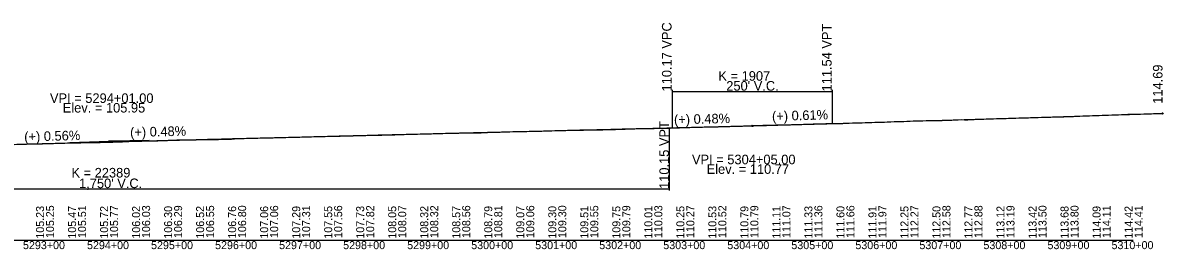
# Model space of a CAD drawing. Extents: x 2121671 to 2169879, y 557274 to 599957.
# Drawn here: x 2158834 to 2160615, y 592693 to 593048 of the extents above; entities that cross this region are included whole.
import ezdxf

# ---------------------------------------------------------------- set-up
doc = ezdxf.new("R2010")
doc.units = 0
for name, color, linetype in [('RD_DDB_GradeTX', 7, 'Continuous'), ('RD_DDB_Profile_EX', 7, 'Continuous'), ('RD_DDB_Profile_Lbl', 7, 'Continuous'), ('RD_DDB_Profile_PR', 7, 'Continuous'), ('RD_DDB_StaTX', 7, 'Continuous'), ('RD_DDB_StripGrade', 7, 'Continuous'), ('RD_DDB_VCLbl', 7, 'Continuous'), ('RD_GPK_Profile_Cell', 7, 'Continuous')]:
    doc.layers.add(name, color=color, linetype=linetype)

msp = doc.modelspace()

# ---------------------------------------------------------------- linework, layer by layer
at = {"layer": 'RD_DDB_GradeTX'}
for p, q in [((2159911.3, 592884.9), (2159972.2, 592886.3)), ((2160035.2, 592888.2), (2159974.2, 592886.4)), ((2158907.3, 592860.5), (2158968.2, 592862.2)), ((2159031.2, 592863.7), (2158970.2, 592862.2))]:
    msp.add_line(p, q, dxfattribs=at)
for centre in [(2160614, 592905.9), (2159973.2, 592886.3), (2158969.2, 592862.2)]:
    msp.add_circle(centre, 1, dxfattribs=at)
at = {"layer": 'RD_DDB_Profile_EX'}
for points in [[(2160004.8, 592887.7), (2160009.8, 592887.8), (2160014.8, 592887.9), (2160019.8, 592888), (2160024.8, 592888.1), (2160029.8, 592888.2), (2160034.8, 592888.3), (2160039.8, 592888.4), (2160044.8, 592888.5), (2160049.8, 592888.7), (2160054.8, 592888.8), (2160059.8, 592888.9), (2160064.8, 592889), (2160069.8, 592889.2), (2160074.8, 592889.3), (2160079.8, 592889.4), (2160084.8, 592889.5), (2160089.8, 592889.8), (2160094.8, 592889.9), (2160099.8, 592889.9), (2160104.8, 592890), (2160109.8, 592890.1), (2160114.8, 592890.3), (2160119.8, 592890.5), (2160124.8, 592890.7), (2160129.8, 592890.9), (2160134.8, 592891), (2160139.8, 592891.2), (2160144.8, 592891.3), (2160149.8, 592891.5), (2160154.8, 592891.6), (2160159.8, 592891.7), (2160164.8, 592891.9), (2160169.8, 592892.1), (2160174.8, 592892.3), (2160179.8, 592892.4), (2160184.8, 592892.6), (2160189.8, 592892.8), (2160194.8, 592893), (2160199.8, 592893.1), (2160204.8, 592893.3), (2160209.8, 592893.4), (2160214.8, 592893.6), (2160219.8, 592893.8), (2160224.8, 592894.1), (2160229.8, 592894.2), (2160234.8, 592894.3), (2160239.8, 592894.4), (2160244.8, 592894.5), (2160249.8, 592894.5), (2160254.8, 592894.6), (2160259.8, 592894.9), (2160264.8, 592895), (2160269.8, 592895), (2160274.8, 592895.1), (2160279.8, 592895.1), (2160284.8, 592895.4), (2160289.8, 592895.6), (2160294.8, 592895.8), (2160299.8, 592896.1), (2160304.8, 592895.9), (2160309.8, 592895.8), (2160314.8, 592896.1), (2160319.8, 592896.4), (2160324.8, 592896.8), (2160329.8, 592896.9), (2160334.8, 592897.1), (2160339.8, 592897.2), (2160344.8, 592897.4), (2160349.8, 592897.6), (2160354.8, 592897.7), (2160359.8, 592897.9), (2160364.8, 592898), (2160369.8, 592898.1), (2160374.8, 592898.3), (2160379.8, 592898.5), (2160384.8, 592898.6), (2160389.8, 592898.8), (2160394.8, 592898.9), (2160399.8, 592899.1), (2160404.8, 592899.1), (2160409.8, 592899.2), (2160414.8, 592899.4), (2160419.8, 592899.7), (2160424.8, 592899.8), (2160429.8, 592899.9), (2160434.8, 592900), (2160439.8, 592900.1), (2160444.8, 592900.3), (2160449.8, 592900.3), (2160454.8, 592900.6), (2160459.8, 592900.7), (2160464.8, 592900.8), (2160469.8, 592900.9), (2160474.8, 592901.1), (2160479.8, 592901.3), (2160484.8, 592901.6), (2160489.8, 592901.8), (2160494.8, 592902), (2160499.8, 592902.2), (2160504.8, 592902.4)], [(2160504.8, 592902.4), (2160509.8, 592902.6), (2160514.8, 592902.8), (2160519.8, 592903), (2160524.8, 592903.1), (2160529.8, 592903.3), (2160534.8, 592903.5), (2160539.8, 592903.7), (2160544.8, 592903.8), (2160549.8, 592904), (2160554.8, 592904.2), (2160559.8, 592904.4), (2160564.8, 592904.5), (2160569.8, 592904.6), (2160574.8, 592904.7), (2160579.8, 592904.9), (2160584.8, 592905), (2160589.8, 592905.1), (2160594.8, 592905.2), (2160599.8, 592905.5), (2160604.8, 592905.6), (2160609.8, 592905.8), (2160614, 592905.9)], [(2159004.8, 592862.3), (2159009.8, 592862.4), (2159014.8, 592862.5), (2159019.8, 592862.6), (2159024.8, 592862.7), (2159029.8, 592862.8), (2159034.8, 592862.9), (2159039.8, 592863), (2159044.8, 592863.2), (2159049.8, 592863.3), (2159054.8, 592863.4), (2159059.8, 592863.6), (2159064.8, 592863.8), (2159069.8, 592864), (2159074.8, 592864.3), (2159079.8, 592864.4), (2159084.8, 592864.4), (2159089.8, 592864.4), (2159094.8, 592864.5), (2159099.8, 592864.6), (2159104.8, 592864.7), (2159109.8, 592864.9), (2159114.8, 592865), (2159119.8, 592865.1), (2159124.8, 592865.1), (2159129.8, 592865.3), (2159134.8, 592865.3), (2159139.8, 592865.3), (2159144.8, 592865.5), (2159149.8, 592865.6), (2159154.8, 592865.8), (2159159.8, 592865.8), (2159164.8, 592866), (2159169.8, 592866.4), (2159174.8, 592866.5), (2159179.8, 592866.7), (2159184.8, 592866.9), (2159189.8, 592867), (2159194.8, 592867.2), (2159199.8, 592867.3), (2159204.8, 592867.4), (2159209.8, 592867.5), (2159214.8, 592867.7), (2159219.8, 592867.8), (2159224.8, 592867.9), (2159229.8, 592868), (2159234.8, 592868.1), (2159239.8, 592868.2), (2159244.8, 592868.3), (2159249.8, 592868.5), (2159254.8, 592868.6), (2159259.8, 592868.7), (2159264.8, 592868.9), (2159269.8, 592869), (2159274.8, 592869.1), (2159279.8, 592869.2), (2159284.8, 592869.4), (2159289.8, 592869.5), (2159294.8, 592869.7), (2159299.8, 592869.9), (2159304.8, 592869.9), (2159309.8, 592870), (2159314.8, 592870.1), (2159319.8, 592870.3), (2159324.8, 592870.4), (2159329.8, 592870.5), (2159334.8, 592870.6), (2159339.8, 592870.7), (2159344.8, 592870.8), (2159349.8, 592870.9), (2159354.8, 592871.1), (2159359.8, 592871.2), (2159364.8, 592871.2), (2159369.8, 592871.1), (2159374.8, 592871.6), (2159379.8, 592871.7), (2159384.8, 592871.8), (2159389.8, 592871.9), (2159394.8, 592872), (2159399.8, 592872.2), (2159404.8, 592872.2), (2159409.8, 592872.4), (2159414.8, 592872.6), (2159419.8, 592872.8), (2159424.8, 592872.9), (2159429.8, 592873.1), (2159434.8, 592873.2), (2159439.8, 592873.4), (2159444.8, 592873.5), (2159449.8, 592873.6), (2159454.8, 592873.8), (2159459.8, 592873.9), (2159464.8, 592874), (2159469.8, 592874.1), (2159474.8, 592874.2), (2159479.8, 592874.4), (2159484.8, 592874.4), (2159489.8, 592874.5), (2159494.8, 592874.7), (2159499.8, 592874.8), (2159504.8, 592874.9)], [(2159504.8, 592874.9), (2159509.8, 592875.1), (2159514.8, 592875.2), (2159519.8, 592875.4), (2159524.8, 592875.5), (2159529.8, 592875.6), (2159534.8, 592875.5), (2159539.8, 592875.6), (2159544.8, 592875.6), (2159549.8, 592875.6), (2159554.8, 592875.8), (2159559.8, 592876.1), (2159564.8, 592876.3), (2159569.8, 592876.5), (2159574.8, 592876.6), (2159579.8, 592876.6), (2159584.8, 592876.8), (2159589.8, 592877), (2159594.8, 592877.1), (2159599.8, 592877.3), (2159604.8, 592877.6), (2159609.8, 592877.6), (2159614.8, 592877.7), (2159619.8, 592877.8), (2159624.8, 592877.9), (2159629.8, 592878), (2159634.8, 592878.1), (2159639.8, 592878.2), (2159644.8, 592878.3), (2159649.8, 592878.4), (2159654.8, 592878.6), (2159659.8, 592878.7), (2159664.8, 592878.9), (2159669.8, 592879), (2159674.8, 592879.2), (2159679.8, 592879.3), (2159684.8, 592879.5), (2159689.8, 592879.6), (2159694.8, 592879.7), (2159699.8, 592879.7), (2159704.8, 592879.7), (2159709.8, 592879.8), (2159714.8, 592879.9), (2159719.8, 592880), (2159724.8, 592880.2), (2159729.8, 592880.3), (2159734.8, 592880.4), (2159739.8, 592880.4), (2159744.8, 592880.6), (2159749.8, 592880.7), (2159754.8, 592880.8), (2159759.8, 592880.9), (2159764.8, 592881.1), (2159769.8, 592881.3), (2159774.8, 592881.4), (2159779.8, 592881.6), (2159784.8, 592881.7), (2159789.8, 592881.8), (2159794.8, 592882), (2159799.8, 592882.1), (2159804.8, 592882.2), (2159809.8, 592882.4), (2159814.8, 592882.4), (2159819.8, 592882.5), (2159824.8, 592882.6), (2159829.8, 592882.7), (2159834.8, 592882.8), (2159839.8, 592882.9), (2159844.8, 592883), (2159849.8, 592883.2), (2159854.8, 592883.3), (2159859.8, 592883.5), (2159864.8, 592883.6), (2159869.8, 592883.8), (2159874.8, 592883.9), (2159879.8, 592884.1), (2159884.8, 592884.2), (2159889.8, 592884.3), (2159894.8, 592884.5), (2159899.8, 592884.6), (2159904.8, 592884.7), (2159909.8, 592884.8), (2159914.8, 592885), (2159919.8, 592885.1), (2159924.8, 592885.3), (2159929.8, 592885.5), (2159934.8, 592885.6), (2159939.8, 592885.7), (2159944.8, 592885.8), (2159949.8, 592885.9), (2159954.8, 592886.1), (2159959.8, 592886.2), (2159964.8, 592886.3), (2159969.8, 592886.4), (2159974.8, 592886.6), (2159979.8, 592886.9), (2159984.8, 592887.1), (2159989.8, 592887.2), (2159994.8, 592887.4), (2159999.8, 592887.6), (2160004.8, 592887.7)], [(2158829.8, 592857.7), (2158834.8, 592857.8), (2158839.8, 592858), (2158844.8, 592858.1), (2158849.8, 592858.3), (2158854.8, 592858.4), (2158859.8, 592858.3), (2158864.8, 592858.5), (2158869.8, 592858.7), (2158874.8, 592858.9), (2158879.8, 592859), (2158884.8, 592859.2), (2158889.8, 592859.4), (2158894.8, 592859.5), (2158899.8, 592859.5), (2158904.8, 592859.7), (2158909.8, 592859.7), (2158914.8, 592859.8), (2158919.8, 592859.8), (2158924.8, 592860), (2158929.8, 592860.1), (2158934.8, 592860.2), (2158939.8, 592860.2), (2158944.8, 592860.3), (2158949.8, 592860.4), (2158954.8, 592860.6), (2158959.8, 592860.8), (2158964.8, 592861), (2158969.8, 592861.1), (2158974.8, 592861.1), (2158979.8, 592861.2), (2158984.8, 592861.4), (2158989.8, 592861.6), (2158994.8, 592861.9), (2158999.8, 592862.1), (2159004.8, 592862.3)]]:
    msp.add_lwpolyline(points, dxfattribs=at)
at = {"layer": 'RD_DDB_Profile_PR'}
for p, q in [((2160098.2, 592890.2), (2160614, 592905.9)), ((2159844.2, 592883.2), (2159848.2, 592883.3))]:
    msp.add_line(p, q, dxfattribs=at)
for points in [[(2159848.2, 592883.3), (2159853.2, 592883.5), (2159858.2, 592883.6), (2159863.2, 592883.7), (2159868.2, 592883.8), (2159873.2, 592883.9), (2159878.2, 592884.1), (2159883.2, 592884.2), (2159888.2, 592884.3), (2159893.2, 592884.4), (2159898.2, 592884.6), (2159903.2, 592884.7), (2159908.2, 592884.8), (2159913.2, 592885), (2159918.2, 592885.1), (2159923.2, 592885.2), (2159928.2, 592885.3), (2159933.2, 592885.5), (2159938.2, 592885.6), (2159943.2, 592885.7), (2159948.2, 592885.9), (2159953.2, 592886), (2159958.2, 592886.1), (2159963.2, 592886.3), (2159968.2, 592886.4), (2159973.2, 592886.5), (2159978.2, 592886.7), (2159983.2, 592886.8), (2159988.2, 592887), (2159993.2, 592887.1), (2159998.2, 592887.2), (2160003.2, 592887.4), (2160008.2, 592887.5), (2160013.2, 592887.7), (2160018.2, 592887.8), (2160023.2, 592887.9), (2160028.2, 592888.1), (2160033.2, 592888.2), (2160038.2, 592888.4), (2160043.2, 592888.5), (2160048.2, 592888.7), (2160053.2, 592888.8), (2160058.2, 592889), (2160063.2, 592889.1), (2160068.2, 592889.3), (2160073.2, 592889.4), (2160078.2, 592889.6), (2160083.2, 592889.7), (2160088.2, 592889.9), (2160093.2, 592890), (2160098.2, 592890.2)], [(2158094.2, 592837.8), (2158129.2, 592838.7), (2158164.2, 592839.7), (2158199.2, 592840.7), (2158234.2, 592841.7), (2158269.2, 592842.6), (2158304.2, 592843.6), (2158339.2, 592844.6), (2158374.2, 592845.5), (2158409.2, 592846.5), (2158444.2, 592847.4), (2158479.2, 592848.4), (2158514.2, 592849.3), (2158549.2, 592850.3), (2158584.2, 592851.2), (2158619.2, 592852.1), (2158654.2, 592853.1), (2158689.2, 592854), (2158724.2, 592854.9), (2158759.2, 592855.9), (2158794.2, 592856.8), (2158829.2, 592857.7), (2158864.2, 592858.6), (2158899.2, 592859.5), (2158934.2, 592860.5), (2158969.2, 592861.4), (2159004.2, 592862.3), (2159039.2, 592863.2), (2159074.2, 592864.1), (2159109.2, 592865), (2159144.2, 592865.9), (2159179.2, 592866.8), (2159214.2, 592867.7), (2159249.2, 592868.5), (2159284.2, 592869.4), (2159319.2, 592870.3), (2159354.2, 592871.2), (2159389.2, 592872.1), (2159424.2, 592873), (2159459.2, 592873.8), (2159494.2, 592874.7), (2159529.2, 592875.6), (2159564.2, 592876.4), (2159599.2, 592877.3), (2159634.2, 592878.1), (2159669.2, 592879), (2159704.2, 592879.9), (2159739.2, 592880.7), (2159774.2, 592881.6), (2159809.2, 592882.4), (2159844.2, 592883.2)]]:
    msp.add_spline(points, degree=3, dxfattribs=at)
at = {"layer": 'RD_DDB_VCLbl'}
for p, q in [((2159848.2, 592942.7), (2159848.2, 592883.3)), ((2159848.2, 592940.2), (2160098.2, 592940.2)), ((2160098.2, 592942.7), (2160098.2, 592890.2)), ((2159844.2, 592785.3), (2159844.2, 592883.2)), ((2158094.2, 592787.8), (2159844.2, 592787.8))]:
    msp.add_line(p, q, dxfattribs=at)
at = {"layer": 'RD_GPK_Profile_Cell'}
msp.add_line((2157368.2, 592707.5), (2160568.2, 592707.5), dxfattribs=at)

# ---------------------------------------------------------------- texts
at = {"layer": 'RD_DDB_GradeTX'}
for s, rotation, p in [('(+) 0.61%', 1.7518, (2160004.3, 592893.9)), ('(+) 0.48%', 1.3765, (2159851.2, 592888.7)), ('(+) 0.56%', 1.6002, (2158836.4, 592861.8)), ('(+) 0.48%', 1.3765, (2159001.7, 592868.9))]:
    msp.add_text(s, height=15, rotation=rotation, dxfattribs=at).set_placement(p)
at = {"layer": 'RD_DDB_Profile_Lbl'}
msp.add_text('114.69', height=15, rotation=90, dxfattribs=at).set_placement((2160614, 592920.9))
for s, p in [('VPI = 5294+01.00', (2158876.4, 592922.2)), ('Elev. = 105.95', (2158896.4, 592907.2)), ('VPI = 5304+05.00', (2159879.1, 592826.3)), ('Elev. = 110.77', (2159902, 592811.3))]:
    msp.add_text(s, height=15, dxfattribs=at).set_placement(p)
at = {"layer": 'RD_DDB_StaTX'}
for s, p in [('5293+00', (2158834.3, 592693.6)), ('5294+00', (2158934.3, 592693.6)), ('5295+00', (2159034.3, 592693.6)), ('5296+00', (2159134.3, 592693.6)), ('5297+00', (2159234.3, 592693.6)), ('5298+00', (2159334.3, 592693.6)), ('5299+00', (2159434.3, 592693.6)), ('5300+00', (2159534.3, 592693.6)), ('5301+00', (2159634.3, 592693.6)), ('5302+00', (2159734.3, 592693.6)), ('5303+00', (2159834.3, 592693.6)), ('5304+00', (2159934.3, 592693.6)), ('5305+00', (2160034.3, 592693.6)), ('5306+00', (2160134.3, 592693.6)), ('5307+00', (2160234.3, 592693.6)), ('5308+00', (2160334.3, 592693.6)), ('5309+00', (2160434.3, 592693.6)), ('5310+00', (2160534.3, 592693.6))]:
    msp.add_text(s, height=12.5, dxfattribs=at).set_placement(p)
at = {"layer": 'RD_DDB_StripGrade'}
for s, height, p in [('110.17 VPC', 15, (2159847.2, 592940.2)), ('111.54 VPT', 15, (2160097.2, 592940.2)), ('110.15 VPT', 15, (2159843.2, 592787.8)), ('105.23', 12.5, (2158867.2, 592710)), ('105.25', 12.5, (2158882.8, 592711)), ('105.47', 12.5, (2158917.2, 592710)), ('105.51', 12.5, (2158932.8, 592711)), ('105.72', 12.5, (2158967.2, 592710)), ('105.77', 12.5, (2158982.8, 592711)), ('106.02', 12.5, (2159017.2, 592710)), ('106.03', 12.5, (2159032.8, 592711)), ('106.30', 12.5, (2159067.2, 592710)), ('106.29', 12.5, (2159082.8, 592711)), ('106.52', 12.5, (2159117.2, 592710)), ('106.55', 12.5, (2159132.8, 592711)), ('106.76', 12.5, (2159167.2, 592710)), ('106.80', 12.5, (2159182.8, 592711)), ('107.06', 12.5, (2159217.2, 592710)), ('107.06', 12.5, (2159232.8, 592711)), ('107.29', 12.5, (2159267.2, 592710)), ('107.31', 12.5, (2159282.8, 592711)), ('107.55', 12.5, (2159317.2, 592710)), ('107.56', 12.5, (2159332.8, 592711)), ('107.73', 12.5, (2159367.2, 592710)), ('107.82', 12.5, (2159382.8, 592711)), ('108.05', 12.5, (2159417.2, 592710)), ('108.07', 12.5, (2159432.8, 592711)), ('108.32', 12.5, (2159467.2, 592710)), ('108.32', 12.5, (2159482.8, 592711)), ('108.57', 12.5, (2159517.2, 592710)), ('108.56', 12.5, (2159532.8, 592711)), ('108.79', 12.5, (2159567.2, 592710)), ('108.81', 12.5, (2159582.8, 592711)), ('109.07', 12.5, (2159617.2, 592710)), ('109.06', 12.5, (2159632.8, 592711)), ('109.30', 12.5, (2159667.2, 592710)), ('109.30', 12.5, (2159682.8, 592711)), ('109.51', 12.5, (2159717.2, 592710)), ('109.55', 12.5, (2159732.8, 592711)), ('109.75', 12.5, (2159767.2, 592710)), ('109.79', 12.5, (2159782.8, 592711)), ('110.01', 12.5, (2159817.2, 592710)), ('110.03', 12.5, (2159832.8, 592711)), ('110.25', 12.5, (2159867.2, 592710)), ('110.27', 12.5, (2159882.8, 592711)), ('110.53', 12.5, (2159917.2, 592710)), ('110.52', 12.5, (2159932.8, 592711)), ('110.79', 12.5, (2159967.2, 592710)), ('110.79', 12.5, (2159982.8, 592711)), ('111.11', 12.5, (2160017.2, 592710)), ('111.07', 12.5, (2160032.8, 592711)), ('111.33', 12.5, (2160067.2, 592710)), ('111.36', 12.5, (2160082.8, 592711)), ('111.60', 12.5, (2160117.2, 592710)), ('111.66', 12.5, (2160132.8, 592711)), ('111.91', 12.5, (2160167.2, 592710)), ('111.97', 12.5, (2160182.8, 592711)), ('112.25', 12.5, (2160217.2, 592710)), ('112.27', 12.5, (2160232.8, 592711)), ('112.50', 12.5, (2160267.2, 592710)), ('112.58', 12.5, (2160282.8, 592711)), ('112.77', 12.5, (2160317.2, 592710)), ('112.88', 12.5, (2160332.8, 592711)), ('113.12', 12.5, (2160367.2, 592710)), ('113.19', 12.5, (2160382.8, 592711)), ('113.42', 12.5, (2160417.2, 592710)), ('113.50', 12.5, (2160432.8, 592711)), ('113.68', 12.5, (2160467.2, 592710)), ('113.80', 12.5, (2160482.8, 592711)), ('114.09', 12.5, (2160517.2, 592710)), ('114.11', 12.5, (2160532.8, 592711)), ('114.42', 12.5, (2160567.2, 592710)), ('114.41', 12.5, (2160582.8, 592711))]:
    msp.add_text(s, height=height, rotation=90, dxfattribs=at).set_placement(p)
at = {"layer": 'RD_DDB_VCLbl'}
for s, p in [('K = 1907', (2159920.4, 592956.9)), ("250' V.C.", (2159932.7, 592941.4)), ('K = 22389', (2158910, 592805.6)), ("1,750' V.C.", (2158921.9, 592789))]:
    msp.add_text(s, height=15, dxfattribs=at).set_placement(p)

doc.saveas('drawing.dxf')
